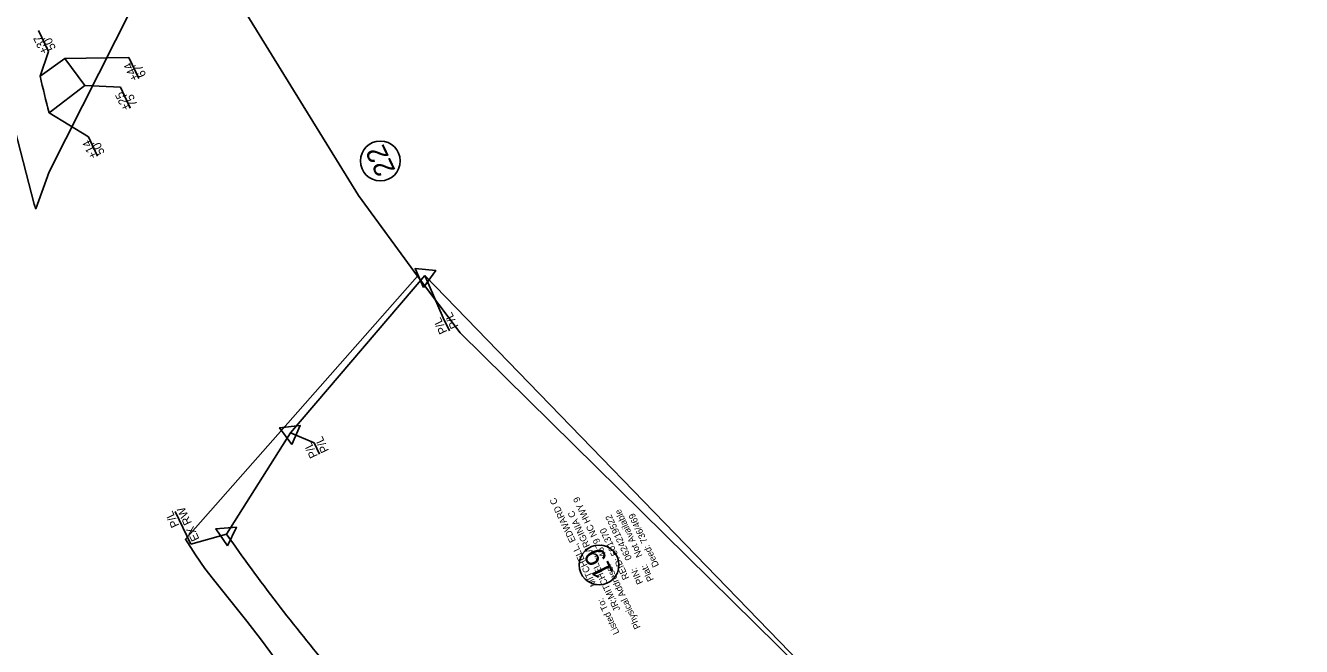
# Model space of a CAD drawing. Extents: x 1019969 to 1024963, y 638146 to 643978.
# Drawn here: x 1022703 to 1023474, y 641561 to 641936 of the extents above; entities that cross this region are included whole.
import ezdxf

# ---------------------------------------------------------------- set-up
doc = ezdxf.new("R2010")
doc.units = 0
for name, color, linetype in [('Old_Level_30', 7, 'Continuous'), ('Pattern 3', 7, 'Continuous'), ('Pattern 5', 7, 'Continuous'), ('Pattern 6', 7, 'Continuous'), ('Prop Easement Construction', 7, 'Continuous'), ('Prop Easement Construction Station Offsets', 7, 'Continuous'), ('Prop Parcel Number CELL', 7, 'Continuous'), ('Prop Parcel Owner Text', 7, 'Continuous'), ('Prop ROW Marker CELL', 7, 'Continuous'), ('Prop ROW RW Lines', 7, 'Continuous'), ('Prop ROW Station Offsets', 7, 'Continuous'), ('Scratch_Level_4', 7, 'Continuous')]:
    doc.layers.add(name, color=color, linetype=linetype)

msp = doc.modelspace()

# ---------------------------------------------------------------- linework, layer by layer
at = {"layer": 'Old_Level_30'}
msp.add_lwpolyline([(1022855.62, 641551.62), (1022845.64, 641565.12), (1022836.69, 641576.62), (1022816.63, 641601.75), (1022811.51, 641608.44), (1022805.81, 641616.69), (1022799.69, 641626.06), (1022939.88, 641784.81), (1022965.69, 641750.69), (1023171, 641548.25)], dxfattribs=at)
at = {"layer": 'Pattern 3'}
for p, q in [((1022944.22, 641785.22), (1022863.17, 641690.41)), ((1023177.12, 641545.08), (1022944.22, 641785.22)), ((1022863.17, 641690.41), (1022824.54, 641629.25))]:
    msp.add_line(p, q, dxfattribs=at)
msp.add_arc((1023780.64, 642297.09), 1166.25, 214.93438, 220.00236, dxfattribs=at)
at = {"layer": 'Pattern 6'}
for p, q in [((1022726.84, 641916.19), (1022711.95, 641905.47)), ((1022739.04, 641899.91), (1022726.84, 641916.19)), ((1022717.37, 641883.39), (1022739.04, 641899.91))]:
    msp.add_line(p, q, dxfattribs=at)
msp.add_arc((1027003.05, 642947.53), 4415.82, 193.64954, 193.94463, dxfattribs=at)
at = {"layer": 'Prop Easement Construction'}
for p, q in [((1022726.84, 641916.19), (1022711.95, 641905.47)), ((1022739.04, 641899.91), (1022726.84, 641916.19)), ((1022739.04, 641899.91), (1022717.37, 641883.39))]:
    msp.add_line(p, q, dxfattribs=at)
at = {"layer": 'Prop Easement Construction Station Offsets'}
for p, q in [((1022711.01, 641933.17), (1022717.09, 641920.33)), ((1022765.59, 641916.78), (1022771.63, 641904.04)), ((1022760.42, 641898.91), (1022766.42, 641886.25)), ((1022741.1, 641868.83), (1022746.62, 641857.17))]:
    msp.add_line(p, q, dxfattribs=at)
for points in [[(1022717.09, 641920.33), (1022711.95, 641905.47)], [(1022765.59, 641916.78), (1022726.84, 641916.19)], [(1022760.42, 641898.91), (1022739.04, 641899.91)], [(1022741.1, 641868.83), (1022717.37, 641883.39)]]:
    msp.add_lwpolyline(points, dxfattribs=at)
at = {"layer": 'Prop Parcel Number CELL'}
for p, q in [((1022917.39, 641854.37), (1022917.39, 641854.37)), ((1023049.49, 641610.57), (1023049.49, 641610.57))]:
    msp.add_line(p, q, dxfattribs=at)
for centre in [(1022917.39, 641854.37), (1023049.49, 641610.57)]:
    msp.add_circle(centre, 12, dxfattribs=at)
at = {"layer": 'Prop ROW Marker CELL'}
for p, q in [((1022944.22, 641785.22), (1022944.22, 641785.22)), ((1022863.17, 641690.41), (1022863.17, 641690.41)), ((1022824.54, 641629.25), (1022824.54, 641629.25))]:
    msp.add_line(p, q, dxfattribs=at)
for points in [[(1022943.48, 641778.04), (1022938.39, 641789.43), (1022950.8, 641788.18)], [(1022863.94, 641683.24), (1022856.58, 641693.33), (1022868.99, 641694.68)], [(1022825.09, 641622.06), (1022818.05, 641632.36), (1022830.49, 641633.33)]]:
    msp.add_lwpolyline(points, close=True, dxfattribs=at)
at = {"layer": 'Prop ROW RW Lines'}
for p, q in [((1022863.17, 641690.41), (1022944.22, 641785.22)), ((1023177.12, 641545.08), (1022944.22, 641785.22)), ((1022824.54, 641629.25), (1022863.17, 641690.41))]:
    msp.add_line(p, q, dxfattribs=at)
for centre, radius, start, end in [((1022167.9, 640774.19), 948.09, 40.00236, 40.00236), ((1023780.64, 642297.09), 1166.25, 214.93438, 220.00236)]:
    msp.add_arc(centre, radius, start, end, dxfattribs=at)
at = {"layer": 'Prop ROW Station Offsets'}
for p, q in [((1022955.34, 641759.72), (1022959.08, 641751.81)), ((1022877.37, 641684.35), (1022880.65, 641677.41)), ((1022793.49, 641642.93), (1022802.89, 641623.07))]:
    msp.add_line(p, q, dxfattribs=at)
for points in [[(1022955.34, 641759.72), (1022944.22, 641785.22)], [(1022877.37, 641684.35), (1022863.17, 641690.41)], [(1022802.89, 641623.07), (1022824.54, 641629.25)]]:
    msp.add_lwpolyline(points, dxfattribs=at)
at = {"layer": 'Scratch_Level_4'}
msp.add_lwpolyline([(1023583.12, 641136.19), (1023429.39, 641289.91), (1023171, 641548.25), (1022965.69, 641750.69), (1022939.88, 641784.81), (1022904.19, 641833.5), (1022797.63, 642006.56), (1022717.5, 641847.75), (1022709.31, 641825.55), (1022708.37, 641828.25), (1022696.87, 641872.69), (1022692.62, 641888.75), (1022682, 641925.56), (1022675.88, 641947.75)], dxfattribs=at)

# ---------------------------------------------------------------- texts
at = {"layer": 'Pattern 5'}
for s, p in [('MITCHELL, EDWARD C ', (1023048.13, 641598.63)), ('4679 NC HWY 9', (1023054.09, 641616.4)), ('JR;MITCHELL, VIRGINIA C', (1023062.34, 641583.8)), ('0624219522', (1023069.39, 641614.48)), ('Not Available', (1023075.76, 641616.21)), ('736/469', (1023078.9, 641624.77)), ('501370', (1023060.9, 641617.22)), ('Deed:', (1023085.75, 641610.31)), ('REID:', (1023067.75, 641602.76)), ('Physical Address:', (1023074.64, 641573.02)), ('PIN:', (1023076.24, 641600.02)), ('Plat:', (1023082.61, 641601.75)), ('Listed To:', (1023061.82, 641569.71))]:
    msp.add_text(s, height=4, rotation=115.34303, dxfattribs=at).set_placement(p)
at = {"layer": 'Prop Easement Construction Station Offsets'}
for s, p in [('+37', (1022717.06, 641920.32)), ("50'", (1022721.63, 641922.49)), ('+44', (1022771.6, 641904.03)), ("67'", (1022776.17, 641906.19)), ('+25', (1022766.4, 641886.24)), ("75'", (1022770.96, 641888.41)), ('+14', (1022746.59, 641857.16)), ("50'", (1022751.16, 641859.32))]:
    msp.add_text(s, height=5, rotation=115.34303, dxfattribs=at).set_placement(p)
at = {"layer": 'Prop Parcel Owner Text'}
for s, p in [('22', (1022926.73, 641848.85)), ('19', (1023058.47, 641605.8))]:
    msp.add_text(s, height=12.15, rotation=115.34303, dxfattribs=at).set_placement(p)
at = {"layer": 'Prop ROW Station Offsets'}
for s, p in [('P/L', (1022964.71, 641754.53)), ('P/L', (1022957.93, 641751.32)), ('P/L', (1022879.73, 641676.44)), ('P/L', (1022886.51, 641679.65)), ('P/L', (1022796.08, 641634.53)), ('EX RW', (1022808.28, 641626.29))]:
    msp.add_text(s, height=5, rotation=115.34303, dxfattribs=at).set_placement(p)

doc.saveas('drawing.dxf')
